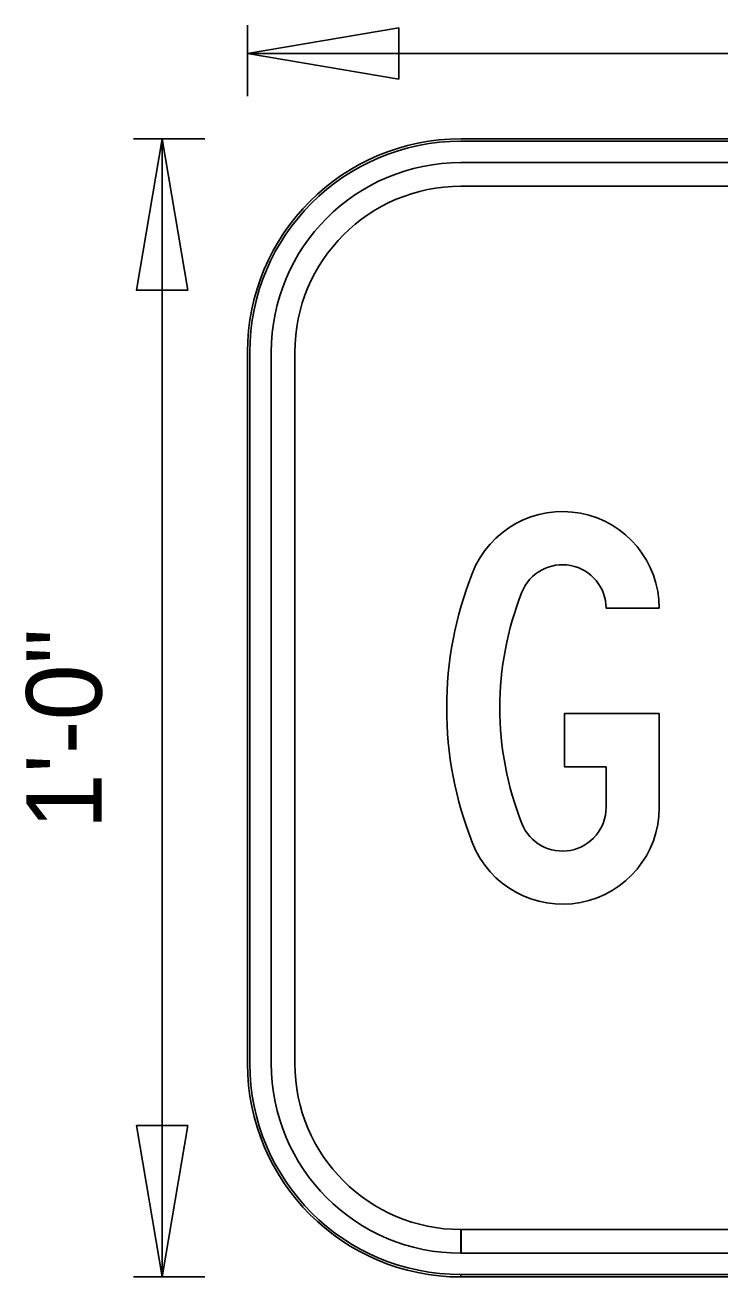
# Model space of a CAD drawing. Extents: x 0 to 770, y 0 to 495.
# Drawn here: x 223.6 to 255.9, y 398.6 to 456.7 of the extents above; entities that cross this region are included whole.
import ezdxf

# ---------------------------------------------------------------- set-up
doc = ezdxf.new("R2010")
doc.units = 0
for name, color, linetype in [('Dimension', 7, 'Continuous'), ('GSBWFill', 7, 'Continuous'), ('GSColorFill', 7, 'Continuous'), ('GSDims', 7, 'Continuous'), ('GSOutline', 7, 'Continuous'), ('TextStructures', 7, 'Continuous')]:
    doc.layers.add(name, color=color, linetype=linetype)

msp = doc.modelspace()

# ---------------------------------------------------------------- linework, layer by layer
at = {"layer": 'Dimension'}
for points in [[(233.956, 455.354), (240.973, 454.166), (240.973, 456.543)], [(229.998, 451.396), (228.809, 444.379), (231.186, 444.379)], [(229.998, 398.618), (231.186, 405.635), (228.809, 405.635)]]:
    msp.add_lwpolyline(points, close=True, dxfattribs=at)
at = {"layer": 'GSBWFill'}
for p, q in [((329.616, 451.396), (243.852, 451.396)), ((329.616, 450.297), (243.852, 450.297)), ((243.852, 449.197), (329.616, 449.197)), ((233.956, 441.5), (233.956, 408.514)), ((235.056, 441.5), (235.056, 408.514)), ((236.155, 408.514), (236.155, 441.5)), ((250.581, 429.625), (253.044, 429.625)), ((250.581, 422.28), (250.581, 420.389)), ((243.852, 399.718), (243.852, 400.817)), ((329.616, 400.817), (243.863, 400.817)), ((243.863, 400.817), (243.863, 399.718)), ((243.863, 399.718), (329.616, 399.718)), ((243.852, 398.618), (329.616, 398.618))]:
    msp.add_line(p, q, dxfattribs=at)
msp.add_lwpolyline([(253.044, 420.389), (253.044, 424.743), (248.646, 424.743), (248.646, 422.28), (250.581, 422.28)], dxfattribs=at)
for centre, radius, start, end in [((243.852, 441.5), 9.896, 90, 180), ((243.852, 441.5), 8.796, 90, 180), ((243.852, 441.5), 7.697, 90, 180), ((248.558, 429.625), 4.486, 0, 158.43141), ((248.558, 429.625), 2.023, 0, 158.43141), ((260.241, 425.007), 17.048, 158.43141, 201.5686), ((260.241, 425.007), 14.585, 158.4314, 201.56859), ((248.558, 420.389), 4.486, 201.56859, 0), ((248.558, 420.389), 2.023, 201.56859, 0), ((243.852, 408.514), 9.896, 180, 270), ((243.852, 408.514), 8.796, 180, 270), ((243.852, 408.514), 7.697, 180, 270)]:
    msp.add_arc(centre, radius, start, end, dxfattribs=at)
at = {"layer": 'GSColorFill'}
for p, q in [((329.616, 451.396), (243.852, 451.396)), ((329.616, 451.396), (243.852, 451.396)), ((243.852, 451.286), (329.616, 451.286)), ((329.616, 450.297), (243.852, 450.297)), ((243.852, 449.197), (329.616, 449.197)), ((233.956, 441.5), (233.956, 408.514)), ((233.956, 441.5), (233.956, 408.514)), ((234.066, 408.514), (234.066, 441.5)), ((235.056, 441.5), (235.056, 408.514)), ((236.155, 408.514), (236.155, 441.5)), ((250.581, 429.625), (253.044, 429.625)), ((250.581, 422.28), (250.581, 420.389)), ((243.852, 399.718), (243.852, 400.817)), ((329.616, 400.817), (243.863, 400.817)), ((243.863, 400.817), (243.863, 399.718)), ((243.863, 399.718), (329.616, 399.718)), ((243.852, 398.618), (243.852, 398.728)), ((243.852, 398.618), (329.616, 398.618)), ((329.616, 398.728), (243.853, 398.728)), ((243.853, 398.728), (243.853, 398.618)), ((243.853, 398.618), (329.616, 398.618))]:
    msp.add_line(p, q, dxfattribs=at)
msp.add_lwpolyline([(253.044, 420.389), (253.044, 424.743), (248.646, 424.743), (248.646, 422.28), (250.581, 422.28)], dxfattribs=at)
for centre, radius, start, end in [((243.852, 441.5), 9.896, 90, 180), ((243.852, 441.5), 9.896, 90, 180), ((243.852, 441.5), 9.786, 90, 180), ((243.852, 441.5), 8.796, 90, 180), ((243.852, 441.5), 7.697, 90, 180), ((248.558, 429.625), 4.486, 0, 158.43141), ((248.558, 429.625), 2.023, 0, 158.43141), ((260.241, 425.007), 17.048, 158.43141, 201.5686), ((260.241, 425.007), 14.585, 158.4314, 201.56859), ((248.558, 420.389), 4.486, 201.56859, 0), ((248.558, 420.389), 2.023, 201.56859, 0), ((243.852, 408.514), 9.896, 180, 270), ((243.852, 408.514), 9.896, 180, 270), ((243.852, 408.514), 9.786, 180, 270), ((243.852, 408.514), 8.796, 180, 270), ((243.852, 408.514), 7.697, 180, 270)]:
    msp.add_arc(centre, radius, start, end, dxfattribs=at)
at = {"layer": 'GSDims'}
for p, q in [((233.956, 453.375), (233.956, 456.674)), ((233.956, 455.354), (339.512, 455.354)), ((231.977, 451.396), (228.678, 451.396)), ((229.998, 398.618), (229.998, 451.396)), ((231.977, 398.618), (228.678, 398.618))]:
    msp.add_line(p, q, dxfattribs=at)
at = {"layer": 'GSOutline'}
for p, q in [((329.616, 451.396), (243.852, 451.396)), ((329.616, 450.297), (243.852, 450.297)), ((329.616, 449.197), (243.852, 449.197)), ((233.956, 441.5), (233.956, 408.514)), ((235.056, 441.5), (235.056, 408.514)), ((236.155, 441.5), (236.155, 408.514)), ((250.581, 429.625), (253.044, 429.625)), ((250.581, 422.28), (250.581, 420.389)), ((243.852, 400.817), (329.616, 400.817)), ((243.852, 399.718), (329.616, 399.718)), ((243.852, 398.618), (329.616, 398.618))]:
    msp.add_line(p, q, dxfattribs=at)
msp.add_lwpolyline([(253.044, 420.389), (253.044, 424.743), (248.646, 424.743), (248.646, 422.28), (250.581, 422.28)], dxfattribs=at)
for centre, radius, start, end in [((243.852, 441.5), 9.896, 90, 180), ((243.852, 441.5), 8.796, 90, 180), ((243.852, 441.5), 7.697, 90, 180), ((248.558, 429.625), 4.486, 0, 158.43141), ((248.558, 429.625), 2.023, 0, 158.43141), ((260.241, 425.007), 17.048, 158.43141, 201.5686), ((260.241, 425.007), 14.585, 158.4314, 201.56859), ((248.558, 420.389), 4.486, 201.56859, 0), ((248.558, 420.389), 2.023, 201.56859, 0), ((243.852, 408.514), 9.896, 180, 270), ((243.852, 408.514), 8.796, 180, 270), ((243.852, 408.514), 7.697, 180, 270)]:
    msp.add_arc(centre, radius, start, end, dxfattribs=at)

# ---------------------------------------------------------------- texts
at = {"layer": 'TextStructures'}
msp.add_text('1\'-0"', height=3.5, rotation=90, dxfattribs=at).set_placement((227.2, 419.373))

doc.saveas('drawing.dxf')
